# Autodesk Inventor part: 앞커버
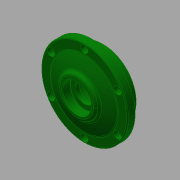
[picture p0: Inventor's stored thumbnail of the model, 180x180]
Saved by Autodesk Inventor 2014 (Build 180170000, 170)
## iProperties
Created: 2016-05
Part Number: 앞커버
Document SubType Name: Modeling
Designer: mduedu
Density: 2.71 g/cm^3
Material: 알루미늄 6061
Appearance: 진녹색
Author: mduedu
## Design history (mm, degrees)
sketch "스케치1"
  geometry: C1 r 35 at (0, 0); C2 r 45 at (0, 0); 1 further point
  constraints: 2 centre point, 2 coincident
  dimensions: "d33" = 90 diameter of C2; "d34" = 70 diameter of C1
extrude "돌출1" new body sketch "스케치1" distance "d0" = 8; taper "d1" = 0 deg
extrude "돌출2" join sketch "스케치1" distance "d2" = 8; taper "d3" = 0 deg; dims "d35" = 12, "d36" = 0
sketch "스케치5"
  geometry: L1 (-45, 8)-(45, 8) reference; L2 (0, 0)-(0, 15); L3 (-45, 0)-(45, 0) reference; L4 (35, 8)-(0, 8); A1 r 91 centre (0, -76) between (35, 8) and (0, 15)
  constraints: 4 end point, 3 point on line, 2 point on circle, 1 centre point, 1 midpoint, 1 perpendicular
  dimensions: "d37" = 35 distance from line of L2 L4.start; "d39" = 7 distance from line of L1 L2.end
revolve "회전2" sketch "스케치5" stored, may be unused: angle "d40" = 90 deg
node "작업 평면1"
sketch "스케치6"
  geometry: C1 r 20 at (0, 0); 1 further point
  constraints: 1 centre point, 1 coincident
  dimensions: "d42" = 40 diameter of C1
extrude "돌출4" join sketch "스케치6" stored distance "d43" = 10; taper "d44" = 0 deg
sketch "스케치4"
  geometry: L1 (0, -12)-(0, 16); L2 (-20, -12)-(-20, 0); L3 (-20, 0)-(-15, 0); L4 (-15, 0)-(-15, 3); L5 (-15, 3)-(-10, 3); L6 (-10, 3)-(-10, 7.5); L7 (-10, 7.5)-(-15, 7.5); L8 (-15, 7.5)-(-15, 16); L9 (35, -12)-(-35, -12) reference; L10 (-20, 16)-(20, 16) reference; 1 further point
  constraints: 16 end point, 6 parallel, 3 point on line, 2 midpoint, 1 perpendicular, 1 vertical
  dimensions: "d15" = 40 diameter of L2 L1; "d16" = 30 diameter of L8 L1; "d18" = 12 distance of L2.start L2.end; "d19" = 3 distance of L3.end L4.end; "d20" = 30 diameter of L4 L1; "d21" = 20 diameter of L6 L1; "d45" = 8.5 distance of L7.end L8.end
revolve "회전1" sketch "스케치4" stored, may be unused: angle "d22" = 90 deg
fillet "모깎기2" dims "d23" = 3
fillet "모깎기3" dims "d24" = 0.3
chamfer "모따기2" distance "d46" = 1; stored, may be unused: second distance "d47" = 2, angle "d48" = 45 deg
fillet "모깎기4" dims "d49" = 3
fillet "모깎기5" dims "d50" = 3
fillet "모깎기6" dims "d51" = 1
sketch "스케치7" dims "d52" = 80
  geometry: C1 r 35.595 at (0, 0) reference; C2 r 44 at (0, 0) reference; 7 further points
  constraints: 2 vertical alignment, 1 coincident, 9 other
  dimensions: "d55" = 360 deg dimension on C1.centre point (0, 40) (derived)
sketch "스케치8"
  geometry: 6 further points
  constraints: 6 other
hole "구멍2" sketch "스케치8" at (-34.641, 20), (-34.641, -20), (0, -40), (34.641, -20), (34.641, 20), (0, 40) diameter "d57" = 4.5; stored, may be unused: countersink angle "d61" = 90 deg, drill point angle "d63" = 0 deg; dims "d58" = 6, "d59" = 8, "d60" = 4.6, "d62" = 8
chamfer "모따기3" distance "d64" = 0.8; stored, may be unused: second distance "d65" = 2, angle "d66" = 30 deg
node "솔리드1"
other parameters: "d41" = 8
